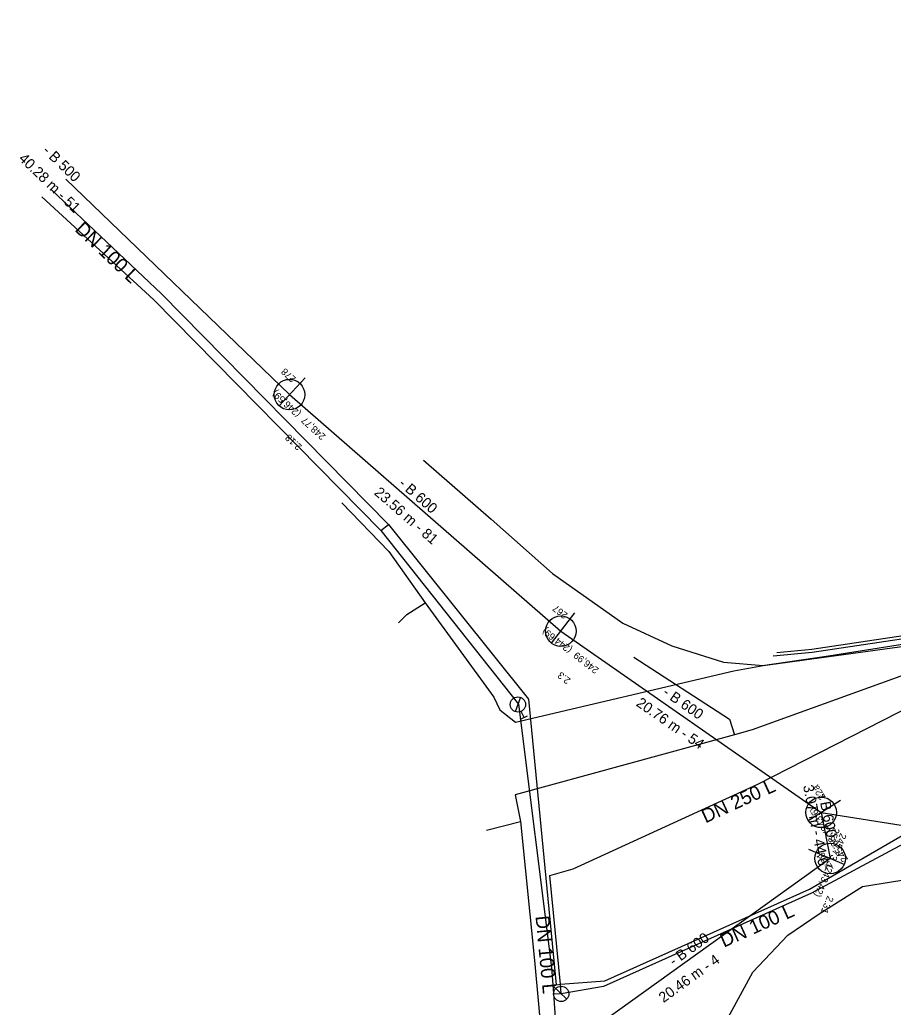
# Model space of a CAD drawing. Extents: x -600636 to -600148, y -1203980 to -1203569.
# Drawn here: x -600636.3 to -600579.1, y -1203804.8 to -1203740.1 of the extents above; entities that cross this region are included whole.
import ezdxf

# ---------------------------------------------------------------- set-up
doc = ezdxf.new("R2010")
doc.units = 0
for name, color, linetype in [('Cetin zam průběh', 7, 'Continuous'), ('EON podzemní NN', 7, 'Continuous'), ('EON podzemní VN', 7, 'Continuous'), ('GasNet NTL', 7, 'Continuous'), ('Implicitní', 7, 'Continuous'), ('VaK Břeclav_kanalizace', 7, 'Continuous'), ('Vak Břeclav_vodovod', 7, 'Continuous')]:
    doc.layers.add(name, color=color, linetype=linetype)

# ---------------------------------------------------------------- blocks, each defined once
blk = doc.blocks.new('MoSymbol 2')
at = {"layer": 'Implicitní'}
blk.add_line((0, 0.0005), (0, -0.00075), dxfattribs=at)
blk.add_circle((0, 0), 0.0005, dxfattribs=at)
blk = doc.blocks.new('MoSymbol 3')
at = {"layer": 'Implicitní'}
for p, q in [((-0.000225, 0.00095), (0.000225, 0.00095)), ((0, 0.00095), (0, 0.0005)), ((-0.000365, -0.000365), (0.000365, 0.000365))]:
    blk.add_line(p, q, dxfattribs=at)
blk.add_circle((0, 0), 0.0005, dxfattribs=at)

msp = doc.modelspace()

# ---------------------------------------------------------------- linework, layer by layer
at = {"layer": 'Cetin zam průběh'}
for points in [[(-600609.86, -1203768.99), (-600605.43, -1203772.85), (-600601.41, -1203776.4), (-600596.81, -1203779.65), (-600593.61, -1203781.13), (-600590.22, -1203782.2), (-600587.64, -1203782.42)], [(-600615.2, -1203771.78), (-600612.13, -1203774.97), (-600609.75, -1203778.32)], [(-600587.64, -1203782.42), (-600577.59, -1203781.05), (-600571.34, -1203779.9), (-600562.09, -1203773.93), (-600559.42, -1203772.74), (-600558.16, -1203771.94), (-600558.14, -1203772.28)], [(-600611.49, -1203779.63), (-600610.96, -1203779.08), (-600609.75, -1203778.32)], [(-600609.75, -1203778.32), (-600605.26, -1203784.51)], [(-600605.26, -1203784.51), (-600604.87, -1203785.33), (-600603.85, -1203786.14), (-600589.55, -1203782.77), (-600587.64, -1203782.42)], [(-600603.85, -1203786.14), (-600589.55, -1203782.77)], [(-600591.27, -1203810.59), (-600590.6, -1203806.73), (-600588.32, -1203802.51), (-600586.01, -1203800.08), (-600583.97, -1203798.69), (-600581.13, -1203796.91), (-600575.98, -1203796.07), (-600574.075, -1203796.372)]]:
    msp.add_lwpolyline(points, dxfattribs=at)
at = {"layer": 'EON podzemní NN'}
for points in [[(-600525.132, -1203747.742), (-600525.004, -1203747.932), (-600525.449, -1203748.251), (-600531.101, -1203752.305), (-600531.678, -1203753.342), (-600534.216, -1203754.907), (-600539.903, -1203758.664), (-600540.687, -1203759.293), (-600544.438, -1203761.852), (-600545.238, -1203762.368), (-600552.695, -1203767.501), (-600554.501, -1203768.539), (-600555.203, -1203768.985), (-600571.205, -1203779.307), (-600573.331, -1203779.913), (-600584.423, -1203781.578), (-600586.99, -1203781.825)], [(-600525.297, -1203747.856), (-600525.279, -1203747.883), (-600531.254, -1203752.169), (-600531.757, -1203753.151), (-600534.324, -1203754.739), (-600540.021, -1203758.502), (-600540.809, -1203758.243), (-600540.807, -1203759.133), (-600544.548, -1203761.686), (-600545.191, -1203761.339), (-600545.348, -1203762.202), (-600552.801, -1203767.331), (-600554.605, -1203768.367), (-600555.135, -1203768.259), (-600555.311, -1203768.817), (-600571.289, -1203779.123), (-600573.373, -1203779.717), (-600584.447, -1203781.38), (-600586.729, -1203781.599)]]:
    msp.add_lwpolyline(points, dxfattribs=at)
at = {"layer": 'EON podzemní VN'}
msp.add_lwpolyline([(-600587.683, -1203782.424), (-600583.35, -1203781.8), (-600578.39, -1203781.01), (-600575.54, -1203780.47), (-600571.28, -1203779.25), (-600564.47, -1203775), (-600557.37, -1203770.49), (-600546.85, -1203763.19), (-600538.93, -1203757.78), (-600533.07, -1203753.94), (-600532.42, -1203753.34), (-600525.77, -1203761.6), (-600524.04, -1203762.18), (-600520.34, -1203759.69), (-600515.99, -1203756.58), (-600509.828, -1203765.1), (-600508.705, -1203765.014), (-600506.819, -1203763.668), (-600505.22, -1203765.813), (-600504.7, -1203765.596)], dxfattribs=at)
at = {"layer": 'GasNet NTL'}
for points in [[(-600486.68, -1203722.48), (-600489.25, -1203724.39), (-600497.78, -1203730.73), (-600501.03, -1203733.15), (-600504.95, -1203736.06), (-600509.64, -1203739.28), (-600520.2, -1203746.52), (-600535.72, -1203757.18), (-600536.81, -1203757.93), (-600541.8, -1203761.35), (-600546.79, -1203764.85), (-600559, -1203773.38), (-600566.88, -1203778.88), (-600575.24, -1203781.91), (-600588.36, -1203786.65), (-600589.51, -1203786.96)], [(-600596.108, -1203781.888), (-600589.83, -1203785.95), (-600589.51, -1203786.96)], [(-600589.51, -1203786.96), (-600603.87, -1203790.9), (-600603.51, -1203792.65), (-600602.6, -1203801.75), (-600602.09, -1203807.23), (-600602.04, -1203807.76), (-600601.82, -1203810.05), (-600601.01, -1203818.68), (-600600.79, -1203823.05), (-600600.33, -1203831.768)], [(-600605.74, -1203793.2), (-600603.51, -1203792.65)]]:
    msp.add_lwpolyline(points, dxfattribs=at)
at = {"layer": 'VaK Břeclav_kanalizace'}
for p, q in [((-600633.26, -1203750.574), (-600618.628, -1203764.69)), ((-600618.628, -1203764.69), (-600600.876, -1203780.176)), ((-600600.876, -1203780.176), (-600583.84, -1203792.047)), ((-600583.84, -1203792.047), (-600583.255, -1203795.061)), ((-600583.84, -1203792.047), (-600558.458, -1203796.062)), ((-600583.255, -1203795.061), (-600599.868, -1203807.001))]:
    msp.add_line(p, q, dxfattribs=at)
at = {"layer": 'Vak Břeclav_vodovod'}
for p, q in [((-600612.656, -1203773.597), (-600612.162, -1203773.201)), ((-600612.656, -1203773.597), (-600603.646, -1203784.964)), ((-600601.355, -1203803.909), (-600600.849, -1203803.933))]:
    msp.add_line(p, q, dxfattribs=at)
for points in [[(-600612.162, -1203773.201), (-600627.017, -1203758.086), (-600634.211, -1203751.28)], [(-600634.836, -1203751.743), (-600627.511, -1203758.482), (-600612.656, -1203773.597)], [(-600612.162, -1203773.201), (-600602.995, -1203784.637), (-600601.189, -1203803.343), (-600600.899, -1203803.294), (-600597.986, -1203803.077), (-600584.599, -1203797.079), (-600575.117, -1203791.572), (-600573.857, -1203790.834), (-600573.636, -1203791.26), (-600573.583, -1203791.689)], [(-600600.849, -1203803.933), (-600600.899, -1203803.294), (-600601.584, -1203796.186), (-600600.078, -1203795.751), (-600587.99, -1203790.2), (-600577.783, -1203784.972), (-600568.695, -1203781.296)], [(-600603.646, -1203784.964), (-600601.496, -1203802.202), (-600601.355, -1203803.909)], [(-600574.494, -1203791.995), (-600584.471, -1203797.336), (-600598.082, -1203803.451), (-600600.849, -1203803.933)], [(-600601.355, -1203803.909), (-600600.518, -1203815.976), (-600600.505, -1203816.572)]]:
    msp.add_lwpolyline(points, dxfattribs=at)

# ---------------------------------------------------------------- block references
at = {"layer": 'VaK Břeclav_kanalizace'}
for p, xscale, yscale, rotation in [((-600618.628, -1203764.69), 1999.7500312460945, 1999.750031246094, 137.46399104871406), ((-600600.876, -1203780.176), 1999.750031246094, 1999.7500312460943, 142.4307789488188), ((-600583.84, -1203792.047), 1999.7500312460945, 1999.750031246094, 122.28574105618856), ((-600583.255, -1203795.061), 1999.750031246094, 1999.750031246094, -112.84231542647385)]:
    msp.add_blockref('MoSymbol 2', p, dxfattribs=dict(at, xscale=xscale, yscale=yscale, rotation=rotation))
at = {"layer": 'Vak Břeclav_vodovod'}
for name, p, xscale, yscale, rotation in [('MoSymbol 3', (-600603.682, -1203784.981), 999.8750156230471, 999.8750156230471, -154.96493830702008), ('MoSymbol 2', (-600600.849, -1203803.933), 999.875015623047, 999.8750156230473, -134.120714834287)]:
    msp.add_blockref(name, p, dxfattribs=dict(at, xscale=xscale, yscale=yscale, rotation=rotation))

# ---------------------------------------------------------------- texts
at = {"layer": 'VaK Břeclav_kanalizace'}
for s, height, rotation, p in [('- B 500', 0.6824, 316.02788, (-600634.831, -1203748.776)), ('40.28 m - 51', 0.68241, 316.02788, (-600636.404, -1203749.289)), ('278', 0.4549, 137.46399, (-600618.173, -1203763.607)), ('248,77  (246,59)', 0.45494, 137.46399, (-600616.229, -1203767.373)), ('2.18', 0.4549, 137.46399, (-600617.786, -1203768.045)), ('23.56 m - 81', 0.68241, 318.90011, (-600613.139, -1203771.184)), ('- B 600', 0.6824, 318.90011, (-600611.54, -1203770.591)), ('267', 0.4549, 142.43078, (-600600.387, -1203779.052)), ('246,99  (244,69)', 0.45494, 142.43078, (-600598.349, -1203782.646)), ('2.3', 0.4549, 142.43078, (-600600.195, -1203783.326)), ('- B 600', 0.6824, 325.13111, (-600594.263, -1203784.319)), ('20.76 m - 54', 0.68241, 325.13111, (-600596, -1203785.023)), ('3.07 m - 44.6', 0.68241, 280.98676, (-600585.028, -1203790.307)), ('22a', 0.4549, 122.28574, (-600583.522, -1203791.05)), ('- B 600', 0.6824, 280.98676, (-600584.018, -1203790.849)), ('245,68  (243,6)', 0.45494, 122.28574, (-600582.055, -1203795.12)), ('245,73  (243,42)', 0.45494, 247.15768, (-600582.573, -1203793.369)), ('257', 0.4549, 247.15768, (-600583.015, -1203792.992)), ('2.08', 0.4549, 122.28574, (-600583.068, -1203795.617)), ('2.31', 0.4549, 247.15768, (-600583.418, -1203797.475)), ('- B 600', 0.6824, 35.70534, (-600593.488, -1203802.133)), ('20.46 m - 4', 0.68241, 35.70534, (-600594.158, -1203804.538))]:
    msp.add_text(s, height=height, rotation=rotation, dxfattribs=at).set_placement(p)
at = {"layer": 'Vak Břeclav_vodovod'}
for s, rotation, p in [('DN 100 L', 316.58843, (-600632.726, -1203753.938)), ('DN 250 L', 24.66533, (-600591.407, -1203792.77)), ('DN 100 L', 24.19291, (-600590.205, -1203800.91)), ('DN 100 L', 275.51462, (-600602.537, -1203798.85))]:
    msp.add_text(s, height=0.9099, rotation=rotation, dxfattribs=at).set_placement(p)

doc.saveas('drawing.dxf')
